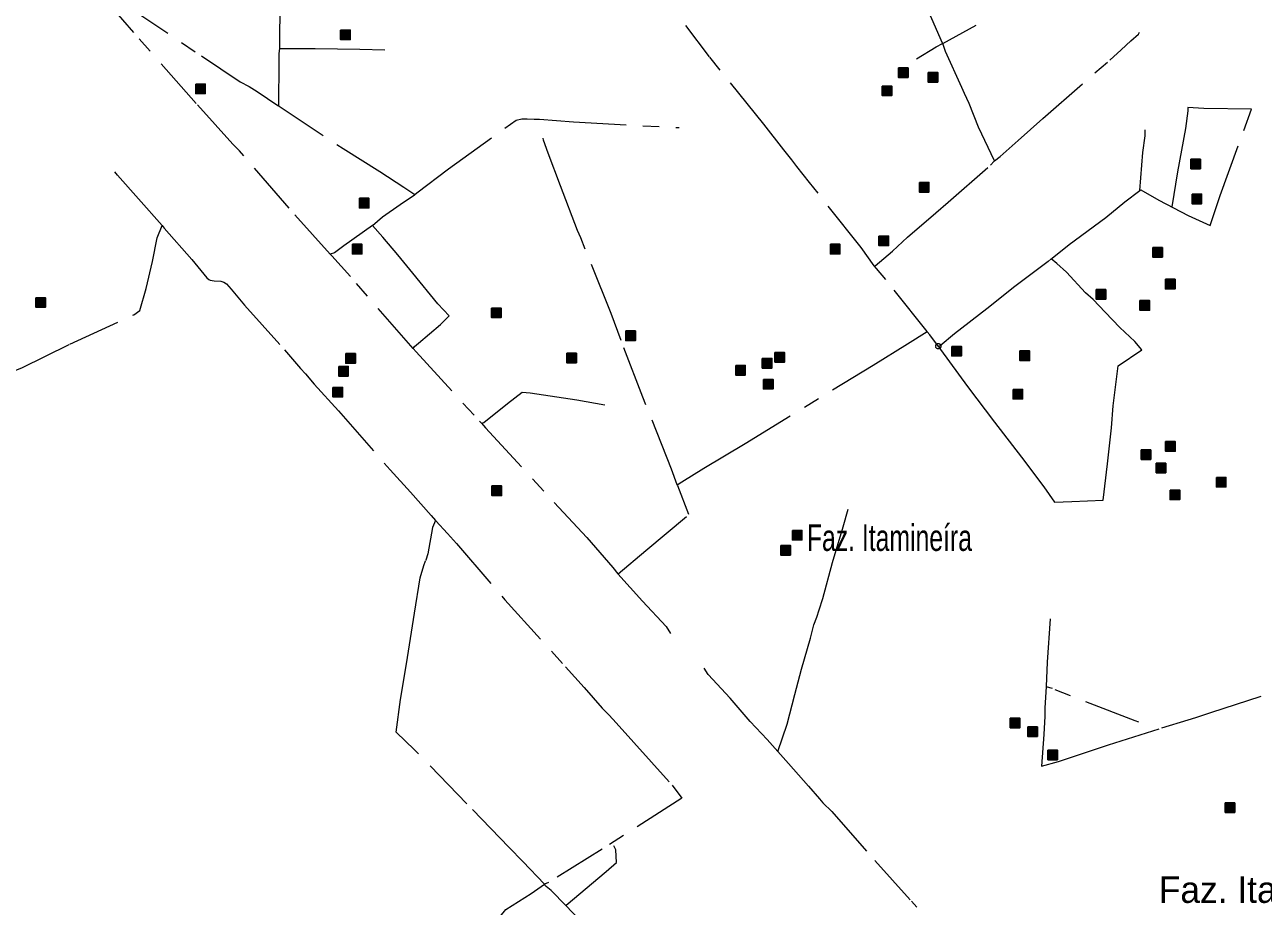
# Model space of a CAD drawing. Extents: x 393.5 to 446.9, y 8064.8 to 8120.4.
# Drawn here: x 405.95 to 413.44, y 8070.34 to 8075.67 of the extents above; entities that cross this region are included whole.
import ezdxf

# ---------------------------------------------------------------- set-up
doc = ezdxf.new("R2010")
doc.units = 0
doc.header["$LTSCALE"] = 0.064
doc.header["$PDMODE"] = 32
doc.header["$PDSIZE"] = 0.032
doc.linetypes.add('DOT_DASHED', pattern=[7.7, 5, -1.2, 0.3, -1.2])
doc.layers.add('2', color=7, linetype='Continuous', lineweight=25)
doc.layers.add('22', color=7, linetype='DOT_DASHED', lineweight=13)
doc.layers.add('61', color=7, linetype='Continuous')

msp = doc.modelspace()

# ---------------------------------------------------------------- hatches: boundary and pattern name
at = {"layer": '2'}
for points in [[(407.8615, 8075.6406), (407.9195, 8075.6406), (407.9195, 8075.5826), (407.8615, 8075.5826)], [(411.2366, 8075.4115), (411.2946, 8075.4115), (411.2946, 8075.3535), (411.2366, 8075.3535)], [(411.4158, 8075.3839), (411.4738, 8075.3839), (411.4738, 8075.3259), (411.4158, 8075.3259)], [(406.9848, 8075.3137), (407.0428, 8075.3137), (407.0428, 8075.2557), (406.9848, 8075.2557)], [(411.1382, 8075.3017), (411.1962, 8075.3017), (411.1962, 8075.2437), (411.1382, 8075.2437)], [(413.0056, 8074.8588), (413.0636, 8074.8588), (413.0636, 8074.8008), (413.0056, 8074.8008)], [(411.3629, 8074.7184), (411.4209, 8074.7184), (411.4209, 8074.6604), (411.3629, 8074.6604)], [(413.0126, 8074.6479), (413.0706, 8074.6479), (413.0706, 8074.5899), (413.0126, 8074.5899)], [(407.9747, 8074.6227), (408.0327, 8074.6227), (408.0327, 8074.5647), (407.9747, 8074.5647)], [(407.9328, 8074.3443), (407.9908, 8074.3443), (407.9908, 8074.2863), (407.9328, 8074.2863)], [(410.8246, 8074.3444), (410.8826, 8074.3444), (410.8826, 8074.2864), (410.8246, 8074.2864)], [(411.1183, 8074.3944), (411.1763, 8074.3944), (411.1763, 8074.3364), (411.1183, 8074.3364)], [(412.7749, 8074.3247), (412.8329, 8074.3247), (412.8329, 8074.2667), (412.7749, 8074.2667)], [(412.8519, 8074.1325), (412.9099, 8074.1325), (412.9099, 8074.0745), (412.8519, 8074.0745)], [(412.4325, 8074.0699), (412.4905, 8074.0699), (412.4905, 8074.0119), (412.4325, 8074.0119)], [(406.0179, 8074.0211), (406.0759, 8074.0211), (406.0759, 8073.9631), (406.0179, 8073.9631)], [(408.7745, 8073.9587), (408.8325, 8073.9587), (408.8325, 8073.9007), (408.7745, 8073.9007)], [(412.6973, 8074.0036), (412.7553, 8074.0036), (412.7553, 8073.9456), (412.6973, 8073.9456)], [(409.5868, 8073.8203), (409.6448, 8073.8203), (409.6448, 8073.7623), (409.5868, 8073.7623)], [(411.5589, 8073.7267), (411.6169, 8073.7267), (411.6169, 8073.6687), (411.5589, 8073.6687)], [(407.8927, 8073.683), (407.9507, 8073.683), (407.9507, 8073.625), (407.8927, 8073.625)], [(409.2299, 8073.6857), (409.2879, 8073.6857), (409.2879, 8073.6277), (409.2299, 8073.6277)], [(410.4124, 8073.6539), (410.4704, 8073.6539), (410.4704, 8073.5959), (410.4124, 8073.5959)], [(410.4892, 8073.6894), (410.5472, 8073.6894), (410.5472, 8073.6314), (410.4892, 8073.6314)], [(411.9713, 8073.699), (412.0293, 8073.699), (412.0293, 8073.641), (411.9713, 8073.641)], [(407.8498, 8073.6051), (407.9078, 8073.6051), (407.9078, 8073.5471), (407.8498, 8073.5471)], [(410.2515, 8073.6113), (410.3095, 8073.6113), (410.3095, 8073.5533), (410.2515, 8073.5533)], [(410.4194, 8073.5273), (410.4774, 8073.5273), (410.4774, 8073.4693), (410.4194, 8073.4693)], [(407.815, 8073.4789), (407.873, 8073.4789), (407.873, 8073.4209), (407.815, 8073.4209)], [(411.9294, 8073.4667), (411.9874, 8073.4667), (411.9874, 8073.4087), (411.9294, 8073.4087)], [(412.8525, 8073.1507), (412.9105, 8073.1507), (412.9105, 8073.0927), (412.8525, 8073.0927)], [(412.7051, 8073.1009), (412.7631, 8073.1009), (412.7631, 8073.0429), (412.7051, 8073.0429)], [(412.7959, 8073.0201), (412.8539, 8073.0201), (412.8539, 8072.9621), (412.7959, 8072.9621)], [(413.1599, 8072.9343), (413.2179, 8072.9343), (413.2179, 8072.8763), (413.1599, 8072.8763)], [(408.7769, 8072.8823), (408.8349, 8072.8823), (408.8349, 8072.8243), (408.7769, 8072.8243)], [(412.8798, 8072.8579), (412.9378, 8072.8579), (412.9378, 8072.7999), (412.8798, 8072.7999)], [(410.5946, 8072.6139), (410.6526, 8072.6139), (410.6526, 8072.5559), (410.5946, 8072.5559)], [(410.5247, 8072.5224), (410.5827, 8072.5224), (410.5827, 8072.4644), (410.5247, 8072.4644)], [(411.913, 8071.4774), (411.971, 8071.4774), (411.971, 8071.4194), (411.913, 8071.4194)], [(412.0188, 8071.4252), (412.0768, 8071.4252), (412.0768, 8071.3672), (412.0188, 8071.3672)], [(412.1405, 8071.2847), (412.1985, 8071.2847), (412.1985, 8071.2267), (412.1405, 8071.2267)], [(413.213, 8070.9656), (413.271, 8070.9656), (413.271, 8070.9076), (413.213, 8070.9076)]]:
    msp.add_hatch(color=256, dxfattribs=at).paths.add_polyline_path(points)

# ---------------------------------------------------------------- linework, layer by layer
for points in [[(407.8615, 8075.6406), (407.9195, 8075.6406), (407.9195, 8075.5826), (407.8615, 8075.5826)], [(411.2366, 8075.4115), (411.2946, 8075.4115), (411.2946, 8075.3535), (411.2366, 8075.3535)], [(411.4158, 8075.3839), (411.4738, 8075.3839), (411.4738, 8075.3259), (411.4158, 8075.3259)], [(406.9848, 8075.3137), (407.0428, 8075.3137), (407.0428, 8075.2557), (406.9848, 8075.2557)], [(411.1382, 8075.3017), (411.1962, 8075.3017), (411.1962, 8075.2437), (411.1382, 8075.2437)], [(413.0056, 8074.8588), (413.0636, 8074.8588), (413.0636, 8074.8008), (413.0056, 8074.8008)], [(411.3629, 8074.7184), (411.4209, 8074.7184), (411.4209, 8074.6604), (411.3629, 8074.6604)], [(413.0126, 8074.6479), (413.0706, 8074.6479), (413.0706, 8074.5899), (413.0126, 8074.5899)], [(407.9747, 8074.6227), (408.0327, 8074.6227), (408.0327, 8074.5647), (407.9747, 8074.5647)], [(407.9328, 8074.3443), (407.9908, 8074.3443), (407.9908, 8074.2863), (407.9328, 8074.2863)], [(410.8246, 8074.3444), (410.8826, 8074.3444), (410.8826, 8074.2864), (410.8246, 8074.2864)], [(411.1183, 8074.3944), (411.1763, 8074.3944), (411.1763, 8074.3364), (411.1183, 8074.3364)], [(412.7749, 8074.3247), (412.8329, 8074.3247), (412.8329, 8074.2667), (412.7749, 8074.2667)], [(412.8519, 8074.1325), (412.9099, 8074.1325), (412.9099, 8074.0745), (412.8519, 8074.0745)], [(412.4325, 8074.0699), (412.4905, 8074.0699), (412.4905, 8074.0119), (412.4325, 8074.0119)], [(406.0179, 8074.0211), (406.0759, 8074.0211), (406.0759, 8073.9631), (406.0179, 8073.9631)], [(408.7745, 8073.9587), (408.8325, 8073.9587), (408.8325, 8073.9007), (408.7745, 8073.9007)], [(412.6973, 8074.0036), (412.7553, 8074.0036), (412.7553, 8073.9456), (412.6973, 8073.9456)], [(409.5868, 8073.8203), (409.6448, 8073.8203), (409.6448, 8073.7623), (409.5868, 8073.7623)], [(411.5589, 8073.7267), (411.6169, 8073.7267), (411.6169, 8073.6687), (411.5589, 8073.6687)], [(407.8927, 8073.683), (407.9507, 8073.683), (407.9507, 8073.625), (407.8927, 8073.625)], [(409.2299, 8073.6857), (409.2879, 8073.6857), (409.2879, 8073.6277), (409.2299, 8073.6277)], [(410.4124, 8073.6539), (410.4704, 8073.6539), (410.4704, 8073.5959), (410.4124, 8073.5959)], [(410.4892, 8073.6894), (410.5472, 8073.6894), (410.5472, 8073.6314), (410.4892, 8073.6314)], [(411.9713, 8073.699), (412.0293, 8073.699), (412.0293, 8073.641), (411.9713, 8073.641)], [(407.8498, 8073.6051), (407.9078, 8073.6051), (407.9078, 8073.5471), (407.8498, 8073.5471)], [(410.2515, 8073.6113), (410.3095, 8073.6113), (410.3095, 8073.5533), (410.2515, 8073.5533)], [(410.4194, 8073.5273), (410.4774, 8073.5273), (410.4774, 8073.4693), (410.4194, 8073.4693)], [(407.815, 8073.4789), (407.873, 8073.4789), (407.873, 8073.4209), (407.815, 8073.4209)], [(411.9294, 8073.4667), (411.9874, 8073.4667), (411.9874, 8073.4087), (411.9294, 8073.4087)], [(412.8525, 8073.1507), (412.9105, 8073.1507), (412.9105, 8073.0927), (412.8525, 8073.0927)], [(412.7051, 8073.1009), (412.7631, 8073.1009), (412.7631, 8073.0429), (412.7051, 8073.0429)], [(412.7959, 8073.0201), (412.8539, 8073.0201), (412.8539, 8072.9621), (412.7959, 8072.9621)], [(413.1599, 8072.9343), (413.2179, 8072.9343), (413.2179, 8072.8763), (413.1599, 8072.8763)], [(408.7769, 8072.8823), (408.8349, 8072.8823), (408.8349, 8072.8243), (408.7769, 8072.8243)], [(412.8798, 8072.8579), (412.9378, 8072.8579), (412.9378, 8072.7999), (412.8798, 8072.7999)], [(410.5946, 8072.6139), (410.6526, 8072.6139), (410.6526, 8072.5559), (410.5946, 8072.5559)], [(410.5247, 8072.5224), (410.5827, 8072.5224), (410.5827, 8072.4644), (410.5247, 8072.4644)], [(411.913, 8071.4774), (411.971, 8071.4774), (411.971, 8071.4194), (411.913, 8071.4194)], [(412.0188, 8071.4252), (412.0768, 8071.4252), (412.0768, 8071.3672), (412.0188, 8071.3672)], [(412.1405, 8071.2847), (412.1985, 8071.2847), (412.1985, 8071.2267), (412.1405, 8071.2267)], [(413.213, 8070.9656), (413.271, 8070.9656), (413.271, 8070.9076), (413.213, 8070.9076)]]:
    msp.add_lwpolyline(points, close=True, dxfattribs=at)
at = {"layer": '22'}
for p, q in [((406.7813, 8074.4579), (406.7817, 8074.4574)), ((409.5384, 8072.35), (409.5405, 8072.3518)), ((412.1297, 8071.6671), (412.1214, 8071.5396)), ((409.2235, 8070.3442), (409.226, 8070.3463))]:
    msp.add_line(p, q, dxfattribs=at)
for points in [[(407.2086, 8074.9506), (406.9878, 8075.1969), (406.6096, 8075.6251), (406.4774, 8075.7783), (406.3878, 8075.8726), (406.3547, 8075.906)], [(406.3767, 8075.9062), (406.55, 8075.7986), (407.0193, 8075.4844), (407.2546, 8075.3272), (407.3091, 8075.2993)], [(407.494, 8075.5289), (407.4939, 8075.6244), (407.5, 8075.9203)], [(411.5036, 8075.5604), (411.4384, 8075.7091), (411.3761, 8075.844), (411.3212, 8075.9705)], [(410.5419, 8074.9148), (410.4213, 8075.0715), (410.0933, 8075.4777), (409.9509, 8075.6674)], [(411.3465, 8075.4653), (411.4649, 8075.5378), (411.5029, 8075.5592), (411.5039, 8075.5598), (411.7061, 8075.6692)], [(412.6419, 8075.5751), (412.6877, 8075.6159), (412.6955, 8075.6281)], [(407.4886, 8075.1828), (407.4906, 8075.4522), (407.4904, 8075.4982), (407.494, 8075.5289)], [(407.494, 8075.5289), (407.7067, 8075.5291), (407.9775, 8075.5242), (408.1299, 8075.521)], [(411.817, 8074.8489), (411.8167, 8074.8495), (411.721, 8075.0537), (411.6633, 8075.1964), (411.6359, 8075.2572), (411.6206, 8075.2927), (411.5207, 8075.5098), (411.5039, 8075.5598), (411.5036, 8075.5604)], [(411.817, 8074.8489), (411.8516, 8074.8754), (411.9613, 8074.9717), (412.109, 8075.1044), (412.5147, 8075.4587), (412.5831, 8075.521), (412.6419, 8075.5751)], [(407.3091, 8075.2993), (407.3565, 8075.269), (407.4815, 8075.1843), (407.4825, 8075.1836), (407.483, 8075.1833), (407.4887, 8075.1794)], [(407.4887, 8075.1794), (407.8773, 8074.9235), (408.0997, 8074.7844), (408.2435, 8074.6901), (408.3096, 8074.6453)], [(412.6972, 8074.6702), (412.702, 8074.6738), (412.8117, 8074.6107), (412.9895, 8074.5189), (413.1228, 8074.4584), (413.1829, 8074.639), (413.325, 8075.0327), (413.3721, 8075.1608), (413.0845, 8075.1667), (412.9878, 8075.1721), (412.9878, 8075.1509), (412.973, 8075.0443), (412.9248, 8074.7822), (412.8896, 8074.5705)], [(408.3096, 8074.6453), (408.3227, 8074.655), (408.5136, 8074.8014), (408.9231, 8075.0958), (408.9574, 8075.103), (408.9898, 8075.103), (409.0331, 8075.1019), (409.0644, 8075.1007), (409.2703, 8075.0846), (409.9093, 8075.05)], [(412.6972, 8074.6702), (412.715, 8074.8993), (412.7287, 8074.9997), (412.7291, 8075.0369)], [(407.7989, 8074.2848), (407.55, 8074.5622), (407.2499, 8074.91), (407.2086, 8074.9506)], [(409.2949, 8074.4285), (409.1922, 8074.6985), (409.1164, 8074.8964), (409.089, 8074.9739), (409.0864, 8074.9867)], [(411.0903, 8074.2134), (411.0109, 8074.3246), (410.6985, 8074.7178), (410.6214, 8074.8152), (410.591, 8074.8557), (410.5419, 8074.9148)], [(406.7813, 8074.4579), (406.6378, 8074.6186), (406.5113, 8074.763), (406.4955, 8074.7833)], [(411.0949, 8074.2145), (411.1993, 8074.3023), (411.2918, 8074.3879), (411.4623, 8074.5344), (411.5374, 8074.5982), (411.7923, 8074.8222), (411.815, 8074.8468), (411.817, 8074.8489)], [(408.0547, 8074.4572), (408.1154, 8074.5106), (408.2219, 8074.5845), (408.3077, 8074.6439)], [(408.307, 8074.6434), (408.3077, 8074.6439), (408.3096, 8074.6453)], [(412.1664, 8074.2597), (412.2699, 8074.3422), (412.4902, 8074.5063), (412.6053, 8074.6006), (412.6972, 8074.6702)], [(406.6461, 8073.9439), (406.6852, 8074.077), (406.7236, 8074.2395), (406.7507, 8074.3839), (406.7813, 8074.4579)], [(406.7817, 8074.4574), (406.7944, 8074.4425), (406.9618, 8074.2519), (407.0527, 8074.1417), (407.0636, 8074.1308), (407.0727, 8074.1272), (407.0963, 8074.1241), (407.1358, 8074.1219)], [(408.0547, 8074.4572), (407.8809, 8074.3345), (407.8249, 8074.2924), (407.7989, 8074.2848)], [(408.2996, 8073.7145), (408.3081, 8073.7254), (408.332, 8073.7467), (408.4651, 8073.8588), (408.5183, 8073.9123), (408.449, 8073.984), (408.299, 8074.1696), (408.2071, 8074.2802), (408.1171, 8074.3869), (408.0547, 8074.4572)], [(409.8985, 8072.8895), (409.8629, 8072.9832), (409.6906, 8073.4198), (409.5582, 8073.7625), (409.4973, 8073.9258), (409.3144, 8074.3831), (409.2949, 8074.4285)], [(407.8076, 8074.2751), (407.8051, 8074.2779), (407.7989, 8074.2848)], [(408.2996, 8073.7145), (407.9205, 8074.1492), (407.8076, 8074.2751)], [(412.1611, 8074.2555), (412.1418, 8074.2401), (411.9405, 8074.0881), (411.7706, 8073.9543), (411.5746, 8073.8022), (411.4886, 8073.73), (411.48, 8073.7265), (411.4788, 8073.726)], [(412.1611, 8074.2555), (412.1661, 8074.2595), (412.1664, 8074.2597)], [(412.4861, 8073.9345), (412.4134, 8074.0105), (412.3684, 8074.0517), (412.2526, 8074.1749), (412.1945, 8074.2273), (412.1611, 8074.2555)], [(411.4094, 8073.8161), (411.1607, 8074.1314), (411.1044, 8074.1983), (411.0903, 8074.2134)], [(411.0917, 8074.2117), (411.0937, 8074.2134), (411.0949, 8074.2145)], [(407.1358, 8074.1219), (407.1548, 8074.1151), (407.1712, 8074.1042), (407.1986, 8074.0719)], [(407.1986, 8074.0719), (407.2397, 8074.0235), (407.2799, 8073.9763), (407.5218, 8073.7049), (407.6194, 8073.5925)], [(405.6433, 8073.8752), (405.8306, 8073.5561), (405.9325, 8073.5979), (406.2237, 8073.7398), (406.6104, 8073.918), (406.6461, 8073.9439)], [(411.4788, 8073.726), (411.4905, 8073.7076), (411.6546, 8073.4847), (411.8168, 8073.2692), (411.9808, 8073.0575), (412.1158, 8072.8777), (412.1814, 8072.784), (412.2845, 8072.7878), (412.4757, 8072.7971), (412.502, 8073.0163), (412.5243, 8073.2342), (412.5363, 8073.3669), (412.5657, 8073.6096), (412.7096, 8073.7051), (412.6665, 8073.7557), (412.5765, 8073.84), (412.4861, 8073.9345)], [(409.8985, 8072.8895), (409.9248, 8072.9064), (410.0581, 8072.9908), (410.3092, 8073.1393), (410.8379, 8073.4641), (411.0835, 8073.614), (411.2916, 8073.7414), (411.4094, 8073.8161)], [(411.4788, 8073.726), (411.4259, 8073.7958), (411.4105, 8073.8147), (411.4094, 8073.8161)], [(408.2996, 8073.7147), (408.3178, 8073.6938), (408.7014, 8073.2742), (408.7145, 8073.2629)], [(407.6194, 8073.5925), (407.6488, 8073.5602), (407.7016, 8073.4984), (407.849, 8073.3366), (408.1607, 8072.9807), (408.2848, 8072.8451), (408.4093, 8072.7031), (408.4357, 8072.6729)], [(408.7145, 8073.2629), (408.7276, 8073.2667), (408.8701, 8073.3809), (408.9597, 8073.4492), (409.0081, 8073.4466), (409.2912, 8073.4035), (409.46, 8073.3735)], [(408.7145, 8073.2629), (408.7389, 8073.2348), (409.1531, 8072.7828), (409.3509, 8072.5701), (409.5084, 8072.3883), (409.5384, 8072.35)], [(409.5405, 8072.3518), (409.708, 8072.4924), (409.9679, 8072.7097), (409.9013, 8072.8823), (409.9004, 8072.8846), (409.8985, 8072.8895)], [(410.7418, 8072.0889), (410.7575, 8072.1324), (410.7781, 8072.2009), (410.8381, 8072.4203), (410.9015, 8072.6345), (410.9324, 8072.7424)], [(408.4357, 8072.6729), (408.4174, 8072.631), (408.3901, 8072.471), (408.3768, 8072.433), (408.3755, 8072.4292)], [(408.4357, 8072.6729), (408.4374, 8072.671), (408.5089, 8072.5939)], [(408.5089, 8072.5939), (408.563, 8072.5346), (408.8552, 8072.1931), (409.2218, 8071.7892), (409.335, 8071.6641), (409.443, 8071.539), (409.4859, 8071.4961), (409.5286, 8071.4499)], [(409.0946, 8070.4726), (408.9635, 8070.6101), (408.8816, 8070.6956), (408.625, 8070.9592), (408.3093, 8071.2865), (408.1983, 8071.3937), (408.2247, 8071.5902), (408.2593, 8071.8066), (408.3076, 8072.1139), (408.3422, 8072.3267), (408.3646, 8072.4019), (408.3755, 8072.4292)], [(409.5384, 8072.35), (409.6879, 8072.1849), (409.8304, 8072.0331), (409.8574, 8071.99)], [(410.5062, 8071.2764), (410.5623, 8071.4415), (410.6104, 8071.6214), (410.6506, 8071.774), (410.7046, 8071.9624), (410.7252, 8072.043), (410.7418, 8072.0889)], [(412.1547, 8072.0786), (412.1356, 8071.8157), (412.1298, 8071.6693), (412.1297, 8071.6671)], [(410.5062, 8071.2764), (410.4415, 8071.3495), (410.3393, 8071.4584), (410.2184, 8071.598), (410.0857, 8071.7424), (410.0618, 8071.7799)], [(413.0351, 8071.4824), (413.1262, 8071.5118), (413.8022, 8071.7301), (413.8058, 8071.7313), (413.8068, 8071.7316)], [(412.6905, 8071.4535), (412.6685, 8071.4608), (412.1676, 8071.6563), (412.1298, 8071.6671)], [(412.1214, 8071.5396), (412.1216, 8071.4901), (412.1161, 8071.3787), (412.1018, 8071.1868), (412.2042, 8071.216), (412.5077, 8071.3165), (412.8294, 8071.4188), (412.9894, 8071.4681), (413.0351, 8071.4824)], [(409.5286, 8071.4499), (409.6358, 8071.3307), (409.8669, 8071.0725), (409.9252, 8070.9943), (409.4435, 8070.6847), (409.119, 8070.484), (409.0946, 8070.4726)], [(410.5062, 8071.2764), (410.5721, 8071.204), (410.6913, 8071.0661), (410.759, 8070.9893)], [(410.759, 8070.9893), (410.7786, 8070.965), (410.8331, 8070.9139), (411.0934, 8070.6168), (411.3147, 8070.3701), (411.3485, 8070.3349)], [(409.226, 8070.3463), (409.2263, 8070.3465), (409.4679, 8070.5504), (409.5298, 8070.605), (409.5261, 8070.6814), (409.5152, 8070.705)], [(408.4822, 8069.8662), (408.5704, 8069.9753), (408.6968, 8070.1177), (408.8606, 8070.3203), (409.0143, 8070.4173), (409.0946, 8070.4726)], [(409.2235, 8070.3442), (409.1354, 8070.4349), (409.1045, 8070.4604), (409.0996, 8070.4665), (409.0982, 8070.4682), (409.0971, 8070.4695), (409.0946, 8070.4726)], [(409.2235, 8070.3442), (409.3447, 8070.2185), (409.4056, 8070.153)]]:
    msp.add_lwpolyline(points, dxfattribs=at)
msp.add_point((411.4774, 8073.7282), dxfattribs=at)

# ---------------------------------------------------------------- texts
at = {"layer": '61', "width": 0.7}
msp.add_text('Faz. Itamineíra', height=0.16, dxfattribs=at).set_placement((410.6823, 8072.4894))
at = {"layer": '61'}
msp.add_text('Faz. Itabaiana', height=0.16, dxfattribs=at).set_placement((412.8112, 8070.3604))

doc.saveas('drawing.dxf')
